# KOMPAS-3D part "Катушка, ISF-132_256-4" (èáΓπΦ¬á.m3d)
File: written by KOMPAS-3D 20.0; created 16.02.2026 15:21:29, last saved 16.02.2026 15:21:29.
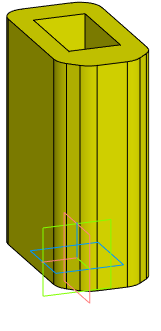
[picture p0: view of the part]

Document properties: Автор: admin; Полное имя файла: P:\INSTART\Технический отдел\ОР\Прочие задачи\КД на номенклатурный ряд\КД на типоразмеры дросселей\Сетевые дроссели ISF\ISF-4\Тип 1\ISF-132_256-4\0723\Новая папка\Катушка.m3d

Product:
- Part/product: Катушка  | designation ISF-132_256-4

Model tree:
1. Операция без истории:1

Expressions: ISF-132_256-4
